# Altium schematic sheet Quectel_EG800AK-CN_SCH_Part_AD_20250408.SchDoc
size A1
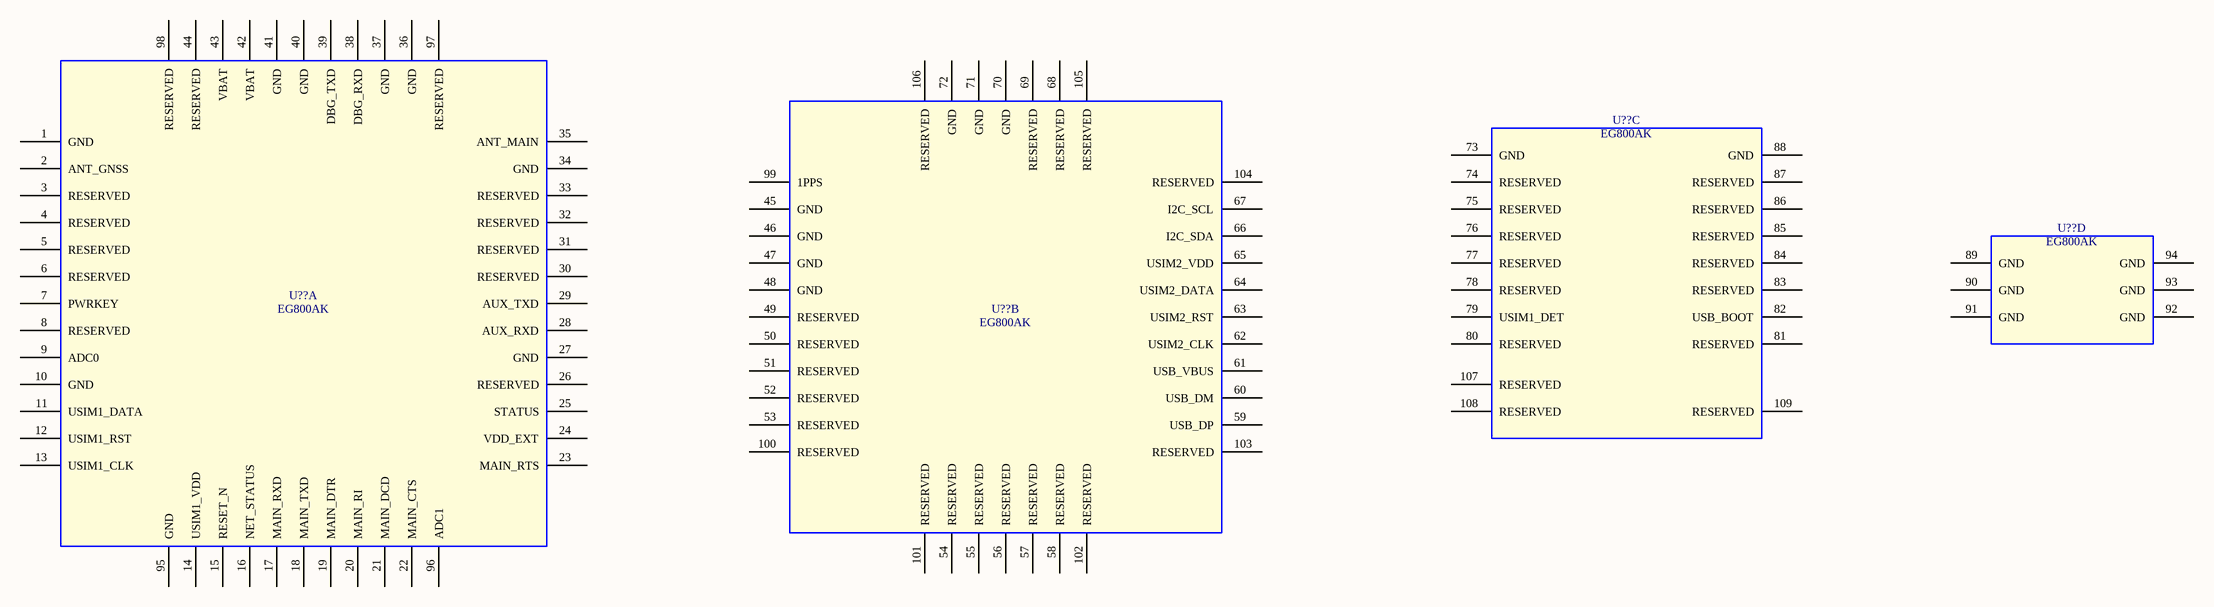
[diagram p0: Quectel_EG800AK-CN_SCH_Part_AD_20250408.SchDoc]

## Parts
(Parts that share a designator on the sheet are numbered #1, #2 ... from top to bottom, then left to right.)
U??#1  EG800AK  [EG800AK]  (part C of 4)
U??#2  EG800AK  [EG800AK]  (part D of 4)
U??#3  EG800AK  [EG800AK]  (part A of 4)
U??#4  EG800AK  [EG800AK]  (part B of 4)

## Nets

Not connected (* = marked no-connect by the designer): U??#1 73(GND) 74(RESERVED) 75(RESERVED) 76(RESERVED) 77(RESERVED) 78(RESERVED) 79(USIM1_DET) 80(RESERVED) 81(RESERVED) 82(USB_BOOT) 83(RESERVED) 84(RESERVED) 85(RESERVED) 86(RESERVED) 87(RESERVED) 88(GND) 107(RESERVED) 108(RESERVED) 109(RESERVED); U??#2 89(GND) 90(GND) 91(GND) 92(GND) 93(GND) 94(GND); U??#3 1(GND) 2(ANT_GNSS) 3(RESERVED) 4(RESERVED) 5(RESERVED) 6(RESERVED) 7(PWRKEY) 8(RESERVED) 9(ADC0) 10(GND) 11(USIM1_DATA) 12(USIM1_RST) 13(USIM1_CLK) 14(USIM1_VDD) 15(RESET_N) 16(NET_STATUS) 17(MAIN_RXD) 18(MAIN_TXD) 19(MAIN_DTR) 20(MAIN_RI) 21(MAIN_DCD) 22(MAIN_CTS) 23(MAIN_RTS) 24(VDD_EXT) 25(STATUS) 26(RESERVED) 27(GND) 28(AUX_RXD) 29(AUX_TXD) 30(RESERVED) 31(RESERVED) 32(RESERVED) 33(RESERVED) 34(GND) 35(ANT_MAIN) 36(GND) 37(GND) 38(DBG_RXD) 39(DBG_TXD) 40(GND) 41(GND) 42(VBAT) 43(VBAT) 44(RESERVED) 95(GND) 96(ADC1) 97(RESERVED) 98(RESERVED); U??#4 45(GND) 46(GND) 47(GND) 48(GND) 49(RESERVED) 50(RESERVED) 51(RESERVED) 52(RESERVED) 53(RESERVED) 54(RESERVED) 55(RESERVED) 56(RESERVED) 57(RESERVED) 58(RESERVED) 59(USB_DP) 60(USB_DM) 61(USB_VBUS) 62(USIM2_CLK) 63(USIM2_RST) 64(USIM2_DATA) 65(USIM2_VDD) 66(I2C_SDA) 67(I2C_SCL) 68(RESERVED) 69(RESERVED) 70(GND) 71(GND) 72(GND) 99(1PPS) 100(RESERVED) 101(RESERVED) 102(RESERVED) 103(RESERVED) 104(RESERVED) 105(RESERVED) 106(RESERVED)

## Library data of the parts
U??#1-U??#4 = EG800AK: EG800AK-CN Module 109PIN 17.7X15.8mm H2.4mm RO; Manufacturer: QUECTEL; Geometry.Height: 2.4mm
